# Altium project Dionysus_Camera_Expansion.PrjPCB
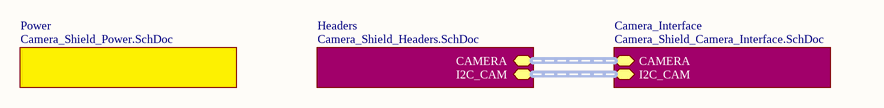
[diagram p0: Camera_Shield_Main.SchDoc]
revision: D
4 sheets, 30 parts. Net scope: hierarchical (ports join the sheet entries above them; power ports are global).
Board file: CAMERA_SHEILD_PCB.PcbDoc
Sheets:
  Camera_Shield_Main.SchDoc
    Camera_Interface = Camera_Shield_Camera_Interface.SchDoc
    Headers = Camera_Shield_Headers.SchDoc
    Power = Camera_Shield_Power.SchDoc

## Sheet Camera_Shield_Main.SchDoc: Block Diagram
size B; CompanyName: Cospan Design; DrawnBy: David McCoy; Engineer: David McCoy; Organization: Cospan Design; DocumentNumber: 1; Revision: .revision; SheetNumber: 1; SheetTotal: 4

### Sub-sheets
Camera_Interface = Camera_Shield_Camera_Interface.SchDoc: I2C_CAM (harness I2C_Harness), CAMERA (harness CAM_Harness)
Headers = Camera_Shield_Headers.SchDoc: I2C_CAM (harness I2C_Harness), CAMERA (harness CAM_Harness)
Power = Camera_Shield_Power.SchDoc: no entries

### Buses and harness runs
harness sheet Camera_Interface/CAMERA = sheet Headers/CAMERA
harness sheet Camera_Interface/I2C_CAM = sheet Headers/I2C_CAM

## Sheet Camera_Shield_Camera_Interface.SchDoc: Camera Interface
size B; CompanyName: Cospan Design; DrawnBy: David McCoy; Engineer: David McCoy; Organization: Cospan Design; DocumentNumber: 3; Revision: .revision; SheetNumber: 3; SheetTotal: 4
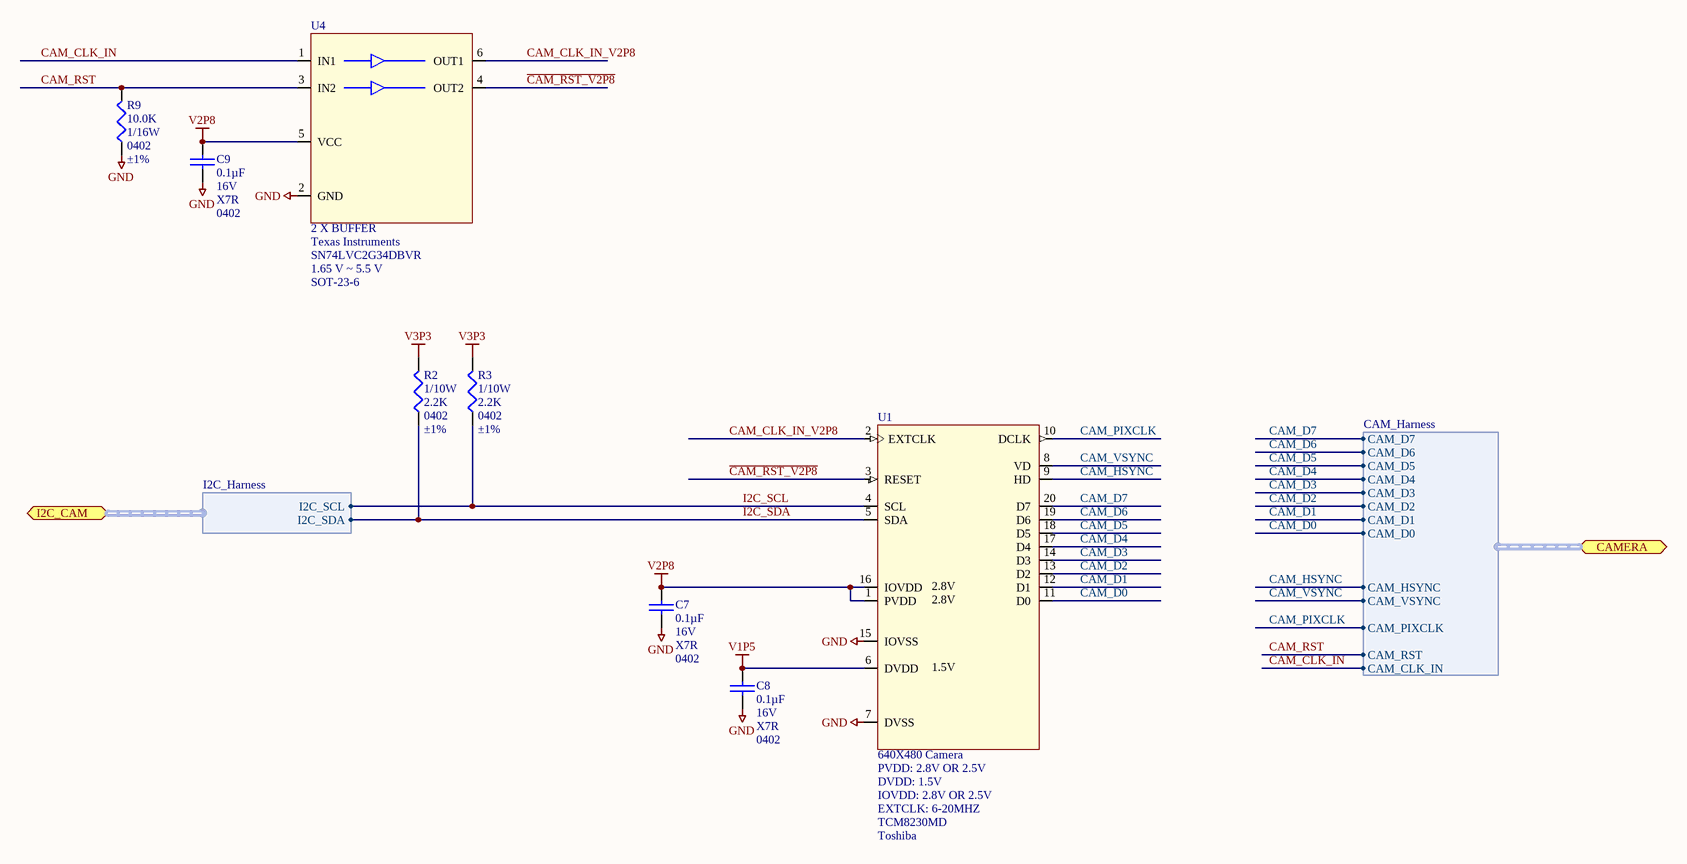
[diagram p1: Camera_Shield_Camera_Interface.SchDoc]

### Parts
C7  Capacitance: 0.1µF  Voltage - Rated: 16V  Temperature Coefficient: X7R  Package / Case: 0402  [C_0402]  (hidden comment: 0.1uF)
C8  Capacitance: 0.1µF  Voltage - Rated: 16V  Temperature Coefficient: X7R  Package / Case: 0402  [C_0402]  (hidden comment: 0.1uF)
C9  Capacitance: 0.1µF  Voltage - Rated: 16V  Temperature Coefficient: X7R  Package / Case: 0402  [C_0402]  (hidden comment: 0.1uF)
R2  Power (Watts): 1/10W  Resistance In Ohms: 2.2K  Case: 0402  Tolerance: ±1%  [ERA-0402]  (hidden comment: 2.2k Ohms)
R3  Power (Watts): 1/10W  Resistance In Ohms: 2.2K  Case: 0402  Tolerance: ±1%  [ERA-0402]  (hidden comment: 2.2k Ohms)
R9  Resistance In Ohms: 10.0K  Power (Watts): 1/16W  Case: 0402  Tolerance: ±1%  [R_0402]  (hidden comment: R_0402_10.0K)
U1  640X480 Camera  PVDD: 2.8V OR 2.5V  DVDD: 1.5V  EXTCLK: 6-20MHZ  Manufacturer: Toshiba  [TCM8230MD]
U4  2 X BUFFER  Manufacturer: Texas Instruments  Manufacturer Part Number: SN74LVC2G34DBVR  Voltage - Supply: 1.65 V ~ 5.5 V  Supplier Device Package: SOT-23-6  [SOT23-6]

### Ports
CAMERA (harness CAM_Harness), I2C_CAM (harness I2C_Harness)

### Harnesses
I2C_Harness: I2C_SDA, I2C_SCL
CAM_Harness: CAM_D7, CAM_D6, CAM_D5, CAM_D4, CAM_D3, CAM_D2, CAM_D1, CAM_D0, CAM_HSYNC, CAM_VSYNC, CAM_PIXCLK, CAM_RST, CAM_CLK_IN

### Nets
GND: C7.1 C8.1 C9.1 R9.2 U1.7(DVSS) U1.15(IOVSS) U4.2(GND)
V1P5: C8.2 U1.6(DVDD)
V2P8: C7.2 C9.2 U1.1(PVDD) U1.16(IOVDD) U4.5(VCC)
V3P3: R2.1 R3.1
~{CAM_RST_V2P8}: U1.3(RESET) U4.4(OUT2)
CAM_CLK_IN: U4.1(IN1) ; port CAMERA.CAM_CLK_IN
CAM_CLK_IN_V2P8: U1.2(EXTCLK) U4.6(OUT1)
CAM_D0: U1.11(D0) ; port CAMERA.CAM_D0
CAM_D1: U1.12(D1) ; port CAMERA.CAM_D1
CAM_D2: U1.13(D2) ; port CAMERA.CAM_D2
CAM_D3: U1.14(D3) ; port CAMERA.CAM_D3
CAM_D4: U1.17(D4) ; port CAMERA.CAM_D4
CAM_D5: U1.18(D5) ; port CAMERA.CAM_D5
CAM_D6: U1.19(D6) ; port CAMERA.CAM_D6
CAM_D7: U1.20(D7) ; port CAMERA.CAM_D7
CAM_HSYNC: U1.9(HD) ; port CAMERA.CAM_HSYNC
CAM_PIXCLK: U1.10(DCLK) ; port CAMERA.CAM_PIXCLK
CAM_RST: R9.1 U4.3(IN2) ; port CAMERA.CAM_RST
CAM_VSYNC: U1.8(VD) ; port CAMERA.CAM_VSYNC
I2C_SCL: R3.2 U1.4(SCL) ; port I2C_CAM.I2C_SCL
I2C_SDA: R2.2 U1.5(SDA) ; port I2C_CAM.I2C_SDA

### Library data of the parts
C7-C9 = C_0402_0.1UF_16V: CAP CER .10UF 16V X7R 0402; Manufacturer: TDK Corporation; Manufacturer Part Number: C1005X7R1C104K; Tolerance: ±10%
R2 R3 = R_0402_2.2K: RES 2.20K OHM 1/10W 1% 0402 SMD; Manufacturer: Yageo; Manufacturer Part Number: RC0402FR-072K2L; Temperature Coefficient: ±100ppm/°C
R9 = R_0402_10.0K: RES 10.0K OHM 1/16W 1% 0402 SMD; Manufacturer: Stackpole Electronics Inc; Manufacturer Part Number: RMCF0402FT10K0; Resistance (Ohms): 10k; Temperature Coefficient: ±100ppm/°C
U1 = U_TCM8230MD_CAMERA: 640 x 480 SPARKFUN CAMERA
U4 = U_SN74LVC2G34DBVR: IC BUFFER DUAL NON-INV SOT23-6; Logic Type: Buffer/Line Driver, Non-Inverting; Number of Bits per Element: 1; Current - Output High, Low: 32mA, 32mA; Number of Elements: 2

## Sheet Camera_Shield_Headers.SchDoc: Shield Headers
size B; CompanyName: Cospan Design; DrawnBy: David McCoy; Engineer: David McCoy; Organization: Cospan Design; DocumentNumber: 2; Revision: .revision; SheetNumber: 2; SheetTotal: 4
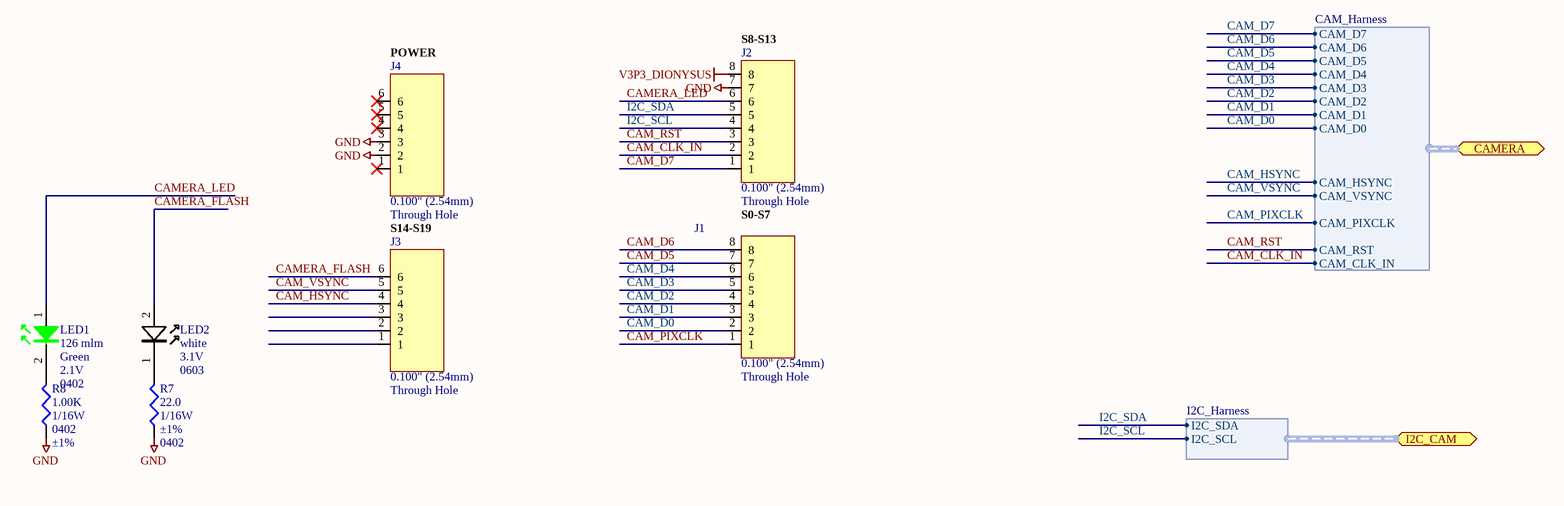
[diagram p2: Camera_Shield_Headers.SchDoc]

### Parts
J1  Pitch: 0.100" (2.54mm)  Mounting Type: Through Hole  [HDR_1X8]  (hidden comment: J_HDR1X8_THRHOLE_VERT)
J2  Pitch: 0.100" (2.54mm)  Mounting Type: Through Hole  [HDR_1X8]  (hidden comment: J_HDR1X8_THRHOLE_VERT)
J3  Pitch: 0.100" (2.54mm)  Mounting Type: Through Hole  [HDR_1X6]  (hidden comment: J_HDR1X6_THRHOLE_VERT)
J4  Pitch: 0.100" (2.54mm)  Mounting Type: Through Hole  [HDR_1X6]  (hidden comment: J_HDR1X6_THRHOLE_VERT)
LED1  Luminous Flux @ Current - Test: 126 mlm  Color: Green  Voltage - Forward (Vf) Typ: 2.1V  Package / Case: 0402  [DIOM1005X07L_GREEN]  (hidden comment: LED_GRN_0402)
LED2  Color: white  Voltage - Forward (Vf) Typ: 3.1V  Package / Case: 0603  [DIOM0603]  (hidden comment: LED_WHITE_0603)
R7  Resistance In Ohms: 22.0  Power (Watts): 1/16W  Tolerance: ±1%  Case: 0402  [ERA-0402]  (hidden comment: R_0402_22.0)
R8  Resistance In Ohms: 1.00K  Power (Watts): 1/16W  Case: 0402  Tolerance: ±1%  [ERA-0402]  (hidden comment: 1.0k Ohms)

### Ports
CAMERA (harness CAM_Harness), I2C_CAM (harness I2C_Harness)

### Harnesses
I2C_Harness: I2C_SDA, I2C_SCL
CAM_Harness: CAM_D7, CAM_D6, CAM_D5, CAM_D4, CAM_D3, CAM_D2, CAM_D1, CAM_D0, CAM_HSYNC, CAM_VSYNC, CAM_PIXCLK, CAM_RST, CAM_CLK_IN

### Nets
GND: J2.7 J4.2 J4.3 R7.2 R8.2
V3P3_DIONYSUS: J2.8
CAM_CLK_IN: J2.2 ; port CAMERA.CAM_CLK_IN
CAM_D0: J1.2 ; port CAMERA.CAM_D0
CAM_D1: J1.3 ; port CAMERA.CAM_D1
CAM_D2: J1.4 ; port CAMERA.CAM_D2
CAM_D3: J1.5 ; port CAMERA.CAM_D3
CAM_D4: J1.6 ; port CAMERA.CAM_D4
CAM_D5: J1.7 ; port CAMERA.CAM_D5
CAM_D6: J1.8 ; port CAMERA.CAM_D6
CAM_D7: J2.1 ; port CAMERA.CAM_D7
CAM_HSYNC: J3.4 ; port CAMERA.CAM_HSYNC
CAM_PIXCLK: J1.1 ; port CAMERA.CAM_PIXCLK
CAM_RST: J2.3 ; port CAMERA.CAM_RST
CAM_VSYNC: J3.5 ; port CAMERA.CAM_VSYNC
CAMERA_FLASH: J3.6 LED2.2
CAMERA_LED: J2.6 LED1.1
I2C_SCL: J2.4 ; port I2C_CAM.I2C_SCL
I2C_SDA: J2.5 ; port I2C_CAM.I2C_SDA
NetLED1_2: LED1.2 R8.1
NetLED2_1: LED2.1 R7.1

Not connected (* = marked no-connect by the designer): J3 1 2 3; J4 1* 4* 5* 6*

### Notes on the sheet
- (near J2) S8-S13
- (near J4) POWER
- S14-S19
- S0-S7

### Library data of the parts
J1 J2 = J_HDR1X8_THRHOLE_VERT: CONN HEADER .100" 12POS TIN PCB; Manufacturer: Samtec; Manufacturer Part Number: TS-108-T-A; Connector Type: Unshrouded; Number of Positions: 8; Number of Positions Loaded: All
J3 J4 = J_HDR1X6_THRHOLE_VERT: CONN HEADER .100" 12POS TIN PCB; Manufacturer: Samtec; Manufacturer Part Number: TSW-106-07-T-S; Connector Type: Unshrouded; Number of Positions: 6; Number of Positions Loaded: All
LED1 = LED_GRN_0402: LED 1X0.5MM 570NM GN WTR CLR SMD; Manufacturer: Kingbright Corp; Manufacturer Part Number: APHHS1005CGCK; Current - Test: 20mA; Wavelength - Peak: 574nm; Millicandela Rating: 40mcd; Lens Type: Clear; Lens Style/Size: Rectangle, 0.8mm x 0.5mm; Viewing Angle: 120°
LED2 = LED_WHITE_0603: LED SMARTLED WHITE DIFF 0603 SMD; Manufacturer: OSRAM Opto Semiconductors Inc; Manufacturer Part Number: LW L283-P2R1-3K8L-1-Z; Millicandela Rating: 98mcd; Current - Test: 10mA; Wavelength - Dominant: 6200K; Viewing Angle: 170°, 130°; Lens Type: Diffused, Tinted; Lens Style/Size: Rectangle with Flat Top, 1.3mm x 0.8mm; Luminous Flux @ Current - Test: 400 mlm
R7 = R_0402_22.0: RES 22.0 OHM 1/16W 1% 0402 SMD; Manufacturer: Vishay Dale; Manufacturer Part Number: CRCW040222R0FKED; Temperature Coefficient: ±100ppm/°C; Resistance (Ohms): 22
R8 = R_0402_1.0K: RES 1.00K OHM 1/16W 1% 0402 SMD; Manufacturer: Yageo; Manufacturer Part Number: RC0402FR-071KL; Resistance (Ohms): 1K; Temperature Coefficient: ±100ppm/°C

## Sheet Camera_Shield_Power.SchDoc: Power
size B; CompanyName: Cospan Design; DrawnBy: David McCoy; Engineer: David McCoy; Organization: Cospan Design; DocumentNumber: 4; Revision: .revision; SheetNumber: 4; SheetTotal: 4
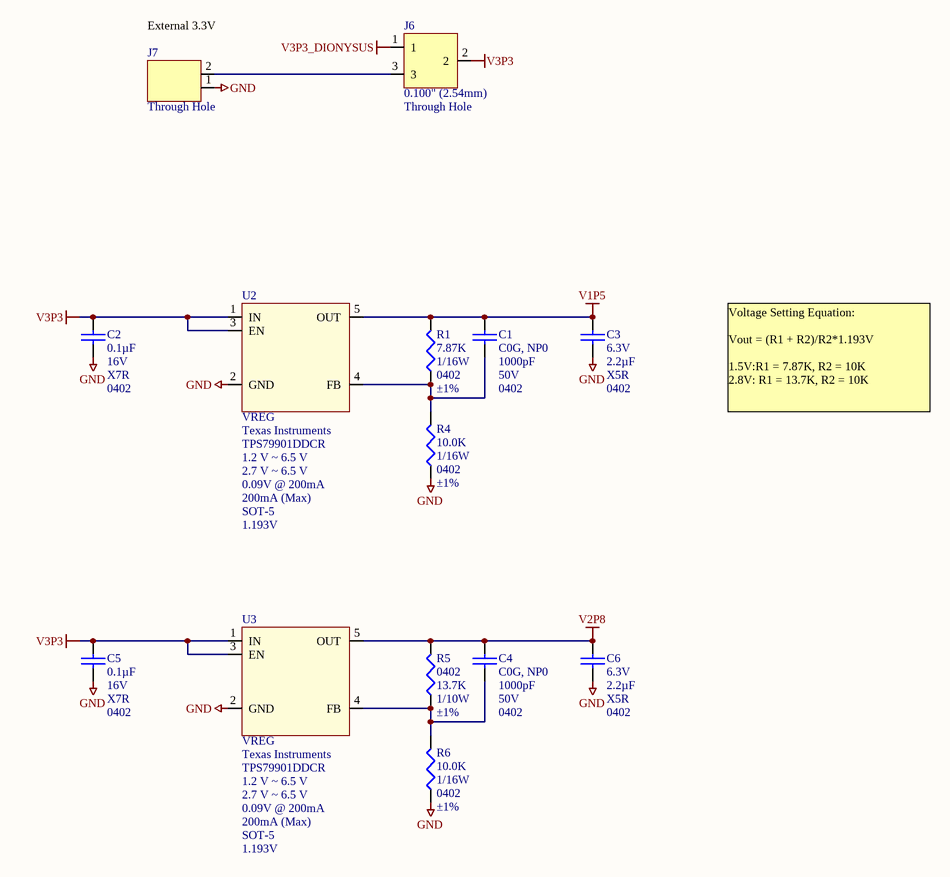
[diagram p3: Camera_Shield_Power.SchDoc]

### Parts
C1  Temperature Coefficient: C0G, NP0  Voltage - Rated: 50V  Package / Case: 0402  [C_ERA-0402]  (hidden comment: 1000pF)
C2  Capacitance: 0.1µF  Voltage - Rated: 16V  Temperature Coefficient: X7R  Package / Case: 0402  [C_0402]  (hidden comment: 0.1uF)
C3  Voltage - Rated: 6.3V  Capacitance: 2.2µF  Temperature Coefficient: X5R  Package / Case: 0402  [C_ERA-0402]  (hidden comment: 2.2uF)
C4  Temperature Coefficient: C0G, NP0  Voltage - Rated: 50V  Package / Case: 0402  [C_ERA-0402]  (hidden comment: 1000pF)
C5  Capacitance: 0.1µF  Voltage - Rated: 16V  Temperature Coefficient: X7R  Package / Case: 0402  [C_0402]  (hidden comment: 0.1uF)
C6  Voltage - Rated: 6.3V  Capacitance: 2.2µF  Temperature Coefficient: X5R  Package / Case: 0402  [C_ERA-0402]  (hidden comment: 2.2uF)
J6  Pitch: 0.100" (2.54mm)  Mounting Type: Through Hole  [HDR_1X3]  (hidden comment: J_HDR1X3_JUMPER_SELECT)
J7  Mounting Type: Through Hole  [HDR_1X2]  (hidden comment: J_HDR1X2_JUMPER)
R1  Resistance In Ohms: 7.87K  Power (Watts): 1/16W  Case: 0402  Tolerance: ±1%  [R_0402]  (hidden comment: R_0402_7.87K)
R4  Resistance In Ohms: 10.0K  Power (Watts): 1/16W  Case: 0402  Tolerance: ±1%  [ERA-0402]  (hidden comment: R_0402_10.0K)
R5  Package / Case: 0402  Resistance (Ohms): 13.7K  Power (Watts): 1/10W  Tolerance: ±1%  [ERA-0402]  (hidden comment: R_0402_13.7K)
R6  Resistance In Ohms: 10.0K  Power (Watts): 1/16W  Case: 0402  Tolerance: ±1%  [ERA-0402]  (hidden comment: R_0402_10.0K)
U2  VREG  Manufacturer: Texas Instruments  Manufacturer Part Number: TPS79901DDCR  Voltage - Output: 1.2 V ~ 6.5 V  Voltage - Input: 2.7 V ~ 6.5 V  Voltage - Dropout (Typical): 0.09V @ 200mA  Current - Output: 200mA (Max)  Supplier Device Package: SOT-5  VREF: 1.193V  [SOT95P280X90-5N]
U3  VREG  Manufacturer: Texas Instruments  Manufacturer Part Number: TPS79901DDCR  Voltage - Output: 1.2 V ~ 6.5 V  Voltage - Input: 2.7 V ~ 6.5 V  Voltage - Dropout (Typical): 0.09V @ 200mA  Current - Output: 200mA (Max)  Supplier Device Package: SOT-5  VREF: 1.193V  [SOT95P280X90-5N]

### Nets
GND: C2.1 C3.1 C5.1 C6.1 J7.1 R4.2 R6.2 U2.2(GND) U3.2(GND)
V1P5: C1.2 C3.2 R1.1 U2.5(OUT)
V2P8: C4.2 C6.2 R5.1 U3.5(OUT)
V3P3: C2.2 C5.2 J6.2 U2.1(IN) U2.3(EN) U3.1(IN) U3.3(EN)
V3P3_DIONYSUS: J6.1
NetC1_1: C1.1 R1.2 R4.1 U2.4(FB)
NetC4_1: C4.1 R5.2 R6.1 U3.4(FB)
NetJ6_3: J6.3 J7.2

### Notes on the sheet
- (near J7) External 3.3V
- Voltage Setting Equation:
  Vout = (R1 + R2)/R2*1.193V
  1.5V:R1 = 7.87K, R2 = 10K
  2.8V: R1 = 13.7K, R2 = 10K

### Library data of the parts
C1 C4 = C_0402_1000PF_50V: CAP CER 1000PF 50V C0G 0402; Manufacturer: Murata Electronics North America; Manufacturer Part Number: GRM1555C1H102JA01D; Tolerance: ±5%
C2 C5 = C_0402_0.1UF_16V: as C7 on sheet Camera_Shield_Camera_Interface
C3 C6 = C_0402_2.2UF: CAP CER 2.2UF 6.3V X5R 0402; Manufacturer: TDK Corporation; Manufacturer Part Number: C1005X5R0J225M; Tolerance: ±20%
J6 = J_HDR1X3_JUMPER_SELECT: CONN HEADER .100" 3POS TIN PCB; Manufacturer: Samtec; Manufacturer Part Number: TSW-103-07-T-S; Connector Type: Unshrouded; Number of Positions: 3; Number of Positions Loaded: All
J7 = J_HDR1X2_JUMPER: CONN HEADER .100" 2POS TIN PCB; Manufacturer: Samtec; Manufacturer Part Number: TSW-102-07-T-S; Number of Positions: 2; Connector Type: Unshrouded; Number of Positions Loaded: All; Pitch: 0.100" (2.54mm); NOTE: This is a 1X12 header
R1 = R_0402_7.87K: RES 7.87K OHM 1/16W 1% 0402 SMD; Manufacturer: Yageo; Manufacturer Part Number: RC0402FR-077K87L; Temperature Coefficient: ±100ppm/°C
R4 R6 = R_0402_10.0K: as R9 on sheet Camera_Shield_Camera_Interface
R5 = R_0402_13.7K: RES 13.7K OHM 1/10W 1% 0402 SMD; Manufacturer: Panasonic - ECG; Manufacturer Part Number: ERJ-2RKF1372X; Temperature Coefficient: ±100ppm/°C
U2 U3 = U_TPS79901DDCR: IC REG LDO ADJ .2A TSOT-23-5; Regulator Topology: Positive Adjustable; Number of Regulators: 1; Current - Limit (Min): 200mA

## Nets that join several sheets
GND: Camera_Shield_Camera_Interface (7 pins), Camera_Shield_Headers (5 pins), Camera_Shield_Power (9 pins)
V1P5: Camera_Shield_Camera_Interface (C8.2 U1.6), Camera_Shield_Power (C1.2 C3.2 R1.1 U2.5)
V2P8: Camera_Shield_Camera_Interface (5 pins), Camera_Shield_Power (C4.2 C6.2 R5.1 U3.5)
V3P3: Camera_Shield_Camera_Interface (R2.1 R3.1), Camera_Shield_Power (7 pins)
V3P3_DIONYSUS: Camera_Shield_Headers (J2.8), Camera_Shield_Power (J6.1)
CAM_CLK_IN: Camera_Shield_Camera_Interface (U4.1), Camera_Shield_Headers (J2.2)
CAM_D0: Camera_Shield_Camera_Interface (U1.11), Camera_Shield_Headers (J1.2)
CAM_D1: Camera_Shield_Camera_Interface (U1.12), Camera_Shield_Headers (J1.3)
CAM_D2: Camera_Shield_Camera_Interface (U1.13), Camera_Shield_Headers (J1.4)
CAM_D3: Camera_Shield_Camera_Interface (U1.14), Camera_Shield_Headers (J1.5)
CAM_D4: Camera_Shield_Camera_Interface (U1.17), Camera_Shield_Headers (J1.6)
CAM_D5: Camera_Shield_Camera_Interface (U1.18), Camera_Shield_Headers (J1.7)
CAM_D6: Camera_Shield_Camera_Interface (U1.19), Camera_Shield_Headers (J1.8)
CAM_D7: Camera_Shield_Camera_Interface (U1.20), Camera_Shield_Headers (J2.1)
CAM_HSYNC: Camera_Shield_Camera_Interface (U1.9), Camera_Shield_Headers (J3.4)
CAM_PIXCLK: Camera_Shield_Camera_Interface (U1.10), Camera_Shield_Headers (J1.1)
CAM_RST: Camera_Shield_Camera_Interface (R9.1 U4.3), Camera_Shield_Headers (J2.3)
CAM_VSYNC: Camera_Shield_Camera_Interface (U1.8), Camera_Shield_Headers (J3.5)
I2C_SCL: Camera_Shield_Camera_Interface (R3.2 U1.4), Camera_Shield_Headers (J2.4)
I2C_SDA: Camera_Shield_Camera_Interface (R2.2 U1.5), Camera_Shield_Headers (J2.5)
